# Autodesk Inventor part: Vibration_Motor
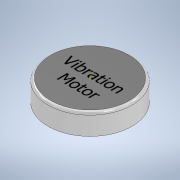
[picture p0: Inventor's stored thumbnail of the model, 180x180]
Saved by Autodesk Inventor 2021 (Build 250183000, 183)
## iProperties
Created: 2021-02
Part Number: Vibration_Motor
Material: Generic
Document SubType Name: Modeling
Designer: callu
Density: 1 g/cm^3
Appearance: Default
Author: callu
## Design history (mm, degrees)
sketch "Sketch1"
  geometry: C1 r 4 at (0, 0); 1 further point
  constraints: 1 centre point, 1 coincident
  dimensions: "d0" = 8 diameter of C1
extrude "Extrusion1" new body sketch "Sketch1" distance "d1" = 2; taper "d2" = 0 deg
sketch "Sketch2"
  geometry: L1 (-2.75, 1)-(3.081, 1); L2 (3.081, 1)-(3.081, -1.712); L3 (3.081, -1.712)-(-2.75, -1.712); L4 (-2.75, -1.712)-(-2.75, 1); 1 further point
  constraints: 2 other
fillet "Fillet1" dims "d4" = 0.25
body "Solid1"
